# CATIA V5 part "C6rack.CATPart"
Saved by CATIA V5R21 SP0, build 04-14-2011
Part number: C6rack
Bounding box of the stored display mesh (mm): x -6.35 to 6.35, y -101.6 to 101.6, z -6.35 to 6.35
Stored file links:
  C:\Users\User\Desktop\B.D.M.A\Chapter6\C6rack.CATPart
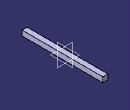
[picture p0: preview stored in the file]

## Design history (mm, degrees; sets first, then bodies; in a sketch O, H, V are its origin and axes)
Body1 (main body)
  Sketch1 on zx-plane, origin (0, 0, 0), H (-1, 0, 0), V (0, 0, 1)
    line L1 (6.35, 6.35) -> (6.35, -6.35)
    line L2 (6.35, -6.35) -> (-6.35, -6.35)
    line L3 (-6.35, -6.35) -> (-6.35, 6.35)
    line L4 (-6.35, 6.35) -> (6.35, 6.35)
    length L4 = 12.7
    length L1 = 12.7
    vertical: L1 V, L3 V
    horizontal: L2 H, L4 H
    equidistance: L1 L3 O, L2 L4 O
  Pad1: profile Sketch1, direction (0, 1, 0), length 101.6, mirrored extent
